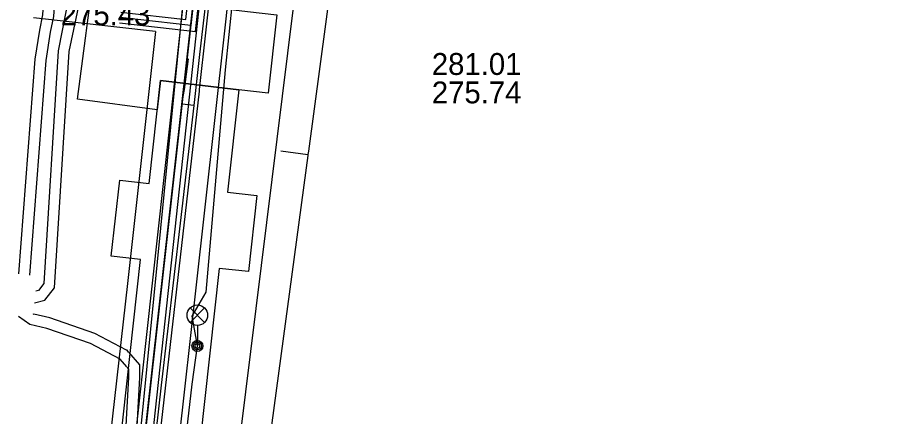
# Model space of a CAD drawing. Extents: x -595540 to -593988, y -1160850 to -1159202.
# Drawn here: x -594124.92 to -594093.22, y -1160478.95 to -1160464.35 of the extents above; entities that cross this region are included whole.
import ezdxf

# ---------------------------------------------------------------- set-up
doc = ezdxf.new("R2010")
doc.units = 0
for name, color, linetype in [('BVK-DESTOVA_popisy', 7, 'Continuous'), ('BVK-DESTOVA_trasa sítě', 7, 'Continuous'), ('BVK-SPLASKOVA_popisy', 7, 'Continuous'), ('BVK-SPLASKOVA_trasa sítě', 7, 'Continuous'), ('BVK-VODOVOD_trasa sítě', 7, 'Continuous'), ('BVK-VODOVOD_trasa zrušené sítě', 7, 'Continuous'), ('CETIN_kabel podzemní', 7, 'Continuous'), ('DESTOVA_trasa neprovozované sítě', 7, 'Continuous'), ('DSP-NN-TEPLARNY_kabel', 7, 'Continuous'), ('EON-NN_kabel', 7, 'Continuous'), ('EON-VN_kabel', 7, 'Continuous'), ('TEPLARNY-ELEKTRO_kabel', 7, 'Continuous'), ('TEPLARNY-HORKOVODY_trasa sítě', 7, 'Continuous'), ('TEPLARNY-HORKOVODY_trasa sítě obvodem', 7, 'Continuous'), ('TEPLARNY-TEPLOVODY_trasa sítě', 7, 'Continuous'), ('TSB_kabel VO', 7, 'Continuous'), ('TSB_kolektor', 7, 'Continuous'), ('TSB_lampy VO', 7, 'Continuous')]:
    doc.layers.add(name, color=color, linetype=linetype)

msp = doc.modelspace()

# ---------------------------------------------------------------- linework, layer by layer
at = {"layer": 'BVK-DESTOVA_trasa sítě'}
msp.add_lwpolyline([(-594112.859, -1160458.585), (-594114.291, -1160469.249), (-594114.307, -1160469.368), (-594114.311, -1160469.398), (-594115.794, -1160480.439), (-594115.833, -1160480.726), (-594115.841, -1160480.786), (-594118, -1160496.861), (-594118.004, -1160496.891), (-594118.009, -1160496.929)], dxfattribs=at)
at = {"layer": 'BVK-SPLASKOVA_popisy'}
msp.add_line((-594109.785, -1160465.658), (-594109.785, -1160465.658), dxfattribs=at)
at = {"layer": 'BVK-SPLASKOVA_trasa sítě'}
msp.add_lwpolyline([(-594114.091, -1160457.889), (-594116.975, -1160481.191), (-594117.014, -1160481.507), (-594118.999, -1160497.545)], dxfattribs=at)
at = {"layer": 'BVK-VODOVOD_trasa sítě'}
for points in [[(-594115.89, -1160444.6), (-594115.94, -1160445.07), (-594116.25, -1160447.88), (-594116.294, -1160448.264), (-594116.92, -1160453.82), (-594117.58, -1160459.76), (-594118.27, -1160465.71), (-594118.48, -1160467.58), (-594118.97, -1160471.88), (-594119.67, -1160477.8), (-594120.34, -1160483.75), (-594121.02, -1160489.68), (-594121.71, -1160495.66), (-594122.21, -1160500.14), (-594122.27, -1160500.66), (-594122.43, -1160502.17)], [(-594118.48, -1160467.58), (-594118.897, -1160467.533), (-594118.86, -1160467.25), (-594118.819, -1160466.987), (-594118.67, -1160465.87)]]:
    msp.add_lwpolyline(points, dxfattribs=at)
at = {"layer": 'BVK-VODOVOD_trasa zrušené sítě'}
msp.add_lwpolyline([(-594122.303, -1160501.51), (-594122.23, -1160501.03), (-594121.73, -1160497.28), (-594118.27, -1160467.05), (-594118.263, -1160466.995), (-594115.72, -1160444.2)], dxfattribs=at)
at = {"layer": 'CETIN_kabel podzemní'}
msp.add_lwpolyline([(-594120.66, -1160482.03), (-594118.21, -1160457.16)], dxfattribs=at)
at = {"layer": 'DESTOVA_trasa neprovozované sítě'}
msp.add_line((-594115.298, -1160469.235), (-594114.307, -1160469.368), dxfattribs=at)
at = {"layer": 'DSP-NN-TEPLARNY_kabel'}
for points in [[(-594121.143, -1160464.161), (-594118.761, -1160464.427), (-594112.865, -1160411.563), (-594119.56, -1160410.802), (-594119.143, -1160407.127), (-594112.454, -1160407.887), (-594102.843, -1160322.736), (-594109.531, -1160321.976), (-594109.114, -1160318.301), (-594102.425, -1160319.061), (-594092.133, -1160228.53), (-594097.433, -1160227.929), (-594097.016, -1160224.253), (-594091.712, -1160224.855), (-594085.261, -1160166.749), (-594090.048, -1160166.163), (-594089.626, -1160162.68), (-594084.872, -1160163.243), (-594081.459, -1160132.499), (-594087.185, -1160131.862)], [(-594121.187, -1160464.559), (-594118.408, -1160464.869), (-594112.423, -1160411.211), (-594119.118, -1160410.45), (-594118.791, -1160407.569), (-594112.102, -1160408.329), (-594102.401, -1160322.384), (-594109.089, -1160321.624), (-594108.762, -1160318.743), (-594102.073, -1160319.503), (-594091.691, -1160228.178)], [(-594091.912, -1160228.354), (-594102.249, -1160319.282), (-594108.938, -1160318.522), (-594109.31, -1160321.8), (-594102.622, -1160322.56), (-594112.278, -1160408.108), (-594118.967, -1160407.348), (-594119.339, -1160410.626), (-594112.644, -1160411.387), (-594118.584, -1160464.648), (-594121.165, -1160464.36)]]:
    msp.add_lwpolyline(points, dxfattribs=at)
at = {"layer": 'EON-NN_kabel'}
for points in [[(-594122.556, -1160445.471), (-594122.597, -1160445.497), (-594122.635, -1160445.889), (-594122.725, -1160446.581), (-594122.486, -1160449.163), (-594122.819, -1160455.327), (-594122.9, -1160461.145), (-594123.016, -1160463.453), (-594123.423, -1160465.583), (-594123.955, -1160474.087), (-594124.149, -1160474.335), (-594124.24, -1160474.359)], [(-594124.294, -1160474.785), (-594123.916, -1160474.688), (-594123.563, -1160474.235), (-594123.023, -1160465.599), (-594122.6, -1160463.579), (-594122.459, -1160460.04), (-594122.421, -1160455.361), (-594122.086, -1160449.177), (-594122.302, -1160446.415), (-594122.222, -1160445.838), (-594122.208, -1160445.663)], [(-594128.953, -1160460.346), (-594128.245, -1160459.666), (-594123.859, -1160460.158), (-594123.491, -1160460.525), (-594123.391, -1160461.016), (-594123.597, -1160464.318), (-594123.719, -1160464.893), (-594123.881, -1160465.933), (-594124.479, -1160473.774)], [(-594128.446, -1160460.412), (-594128.103, -1160460.084), (-594124.043, -1160460.54), (-594123.859, -1160460.723), (-594123.794, -1160461.05), (-594123.994, -1160464.264), (-594124.113, -1160464.821), (-594124.279, -1160465.887), (-594124.876, -1160473.724)], [(-594120.918, -1160477.133), (-594121.168, -1160476.842), (-594122.25, -1160476.275), (-594123.841, -1160475.726), (-594124.463, -1160475.579), (-594124.879, -1160475.286)], [(-594120.858, -1160476.589), (-594120.914, -1160476.524), (-594120.93, -1160476.515), (-594122.091, -1160475.907), (-594123.73, -1160475.341), (-594124.316, -1160475.203), (-594124.347, -1160475.211)], [(-594120.86, -1160476.587), (-594120.454, -1160477.06), (-594120.454, -1160477.521), (-594120.631, -1160480.626), (-594120.758, -1160482.853), (-594120.909, -1160484.458), (-594121.245, -1160487.388), (-594121.808, -1160492.605), (-594122.21, -1160496.156), (-594122.252, -1160498.234), (-594122.328, -1160499.594), (-594122.85, -1160502.414), (-594122.986, -1160503.122)], [(-594120.916, -1160477.135), (-594120.854, -1160477.208), (-594120.854, -1160477.509), (-594121.031, -1160480.604), (-594121.156, -1160482.823), (-594121.307, -1160484.416), (-594121.643, -1160487.344), (-594122.206, -1160492.561), (-594122.61, -1160496.13), (-594122.652, -1160498.218), (-594122.726, -1160499.546), (-594123.244, -1160502.34), (-594123.385, -1160503.08)]]:
    msp.add_lwpolyline(points, dxfattribs=at)
at = {"layer": 'EON-VN_kabel'}
for points in [[(-594095.349, -1160247.589), (-594106.321, -1160343.506), (-594106.366, -1160343.901), (-594106.457, -1160344.697), (-594105.747, -1160344.778), (-594123.196, -1160503.1)], [(-594122.533, -1160503.17), (-594105.303, -1160344.425), (-594106.002, -1160344.346), (-594105.957, -1160343.948), (-594105.911, -1160343.552), (-594094.954, -1160247.658)]]:
    msp.add_lwpolyline(points, dxfattribs=at)
at = {"layer": 'TEPLARNY-ELEKTRO_kabel'}
for points in [[(-594121.143, -1160464.161), (-594118.761, -1160464.427), (-594112.865, -1160411.563), (-594119.56, -1160410.802), (-594119.143, -1160407.127), (-594112.454, -1160407.887), (-594102.843, -1160322.736), (-594109.531, -1160321.976), (-594109.114, -1160318.301), (-594102.425, -1160319.061), (-594092.133, -1160228.53), (-594097.433, -1160227.929), (-594097.016, -1160224.253), (-594091.712, -1160224.855), (-594085.261, -1160166.749), (-594090.048, -1160166.163), (-594089.626, -1160162.68), (-594084.872, -1160163.243), (-594081.459, -1160132.499), (-594087.185, -1160131.862)], [(-594121.187, -1160464.559), (-594118.408, -1160464.869), (-594112.423, -1160411.211), (-594119.118, -1160410.45), (-594118.791, -1160407.569), (-594112.102, -1160408.329), (-594102.401, -1160322.384), (-594109.089, -1160321.624), (-594108.762, -1160318.743), (-594102.073, -1160319.503), (-594091.691, -1160228.178)], [(-594091.912, -1160228.354), (-594102.249, -1160319.282), (-594108.938, -1160318.522), (-594109.31, -1160321.8), (-594102.622, -1160322.56), (-594112.278, -1160408.108), (-594118.967, -1160407.348), (-594119.339, -1160410.626), (-594112.644, -1160411.387), (-594118.584, -1160464.648), (-594121.165, -1160464.36)]]:
    msp.add_lwpolyline(points, dxfattribs=at)
at = {"layer": 'TEPLARNY-HORKOVODY_trasa sítě'}
for p, q in [((-594118.492, -1160463.766), (-594119.659, -1160474.215)), ((-594119.659, -1160474.215), (-594122.628, -1160500.798))]:
    msp.add_line(p, q, dxfattribs=at)
at = {"layer": 'TEPLARNY-HORKOVODY_trasa sítě obvodem'}
for p, q in [((-594114.916, -1160442.994), (-594117.369, -1160464.959)), ((-594119.874, -1160464.868), (-594124.325, -1160464.368)), ((-594119.874, -1160464.868), (-594120.902, -1160474.076)), ((-594117.369, -1160464.959), (-594118.418, -1160474.354)), ((-594120.902, -1160474.076), (-594123.939, -1160501.282)), ((-594118.418, -1160474.354), (-594121.317, -1160500.314))]:
    msp.add_line(p, q, dxfattribs=at)
at = {"layer": 'TEPLARNY-TEPLOVODY_trasa sítě'}
msp.add_lwpolyline([(-594118.533, -1160464.056), (-594120.423, -1160480.943), (-594122.643, -1160500.777), (-594146.3, -1160497.939)], dxfattribs=at)
at = {"layer": 'TSB_kabel VO'}
msp.add_lwpolyline([(-594119.13, -1160482.95), (-594118.54, -1160477.76), (-594118.345, -1160476.366), (-594118.53, -1160475.28), (-594118.03, -1160474.4), (-594117.32, -1160466.27), (-594117.05, -1160463.68), (-594116.52, -1160460.6), (-594116.559, -1160459.42), (-594118.018, -1160458.247), (-594123.237, -1160458.036), (-594123.181, -1160457.489), (-594122.139, -1160448.947), (-594121.383, -1160445.991), (-594120.533, -1160445.877), (-594120.523, -1160444.982), (-594120.12, -1160445.03), (-594117.23, -1160445.35), (-594116.44, -1160439.53), (-594115.77, -1160439.63)], dxfattribs=at)
at = {"layer": 'TSB_kolektor'}
msp.add_lwpolyline([(-594115.445, -1160464.264), (-594115.766, -1160467.127), (-594116.836, -1160467.007), (-594119.696, -1160466.66), (-594119.814, -1160467.737), (-594122.722, -1160467.348), (-594122.072, -1160462.412), (-594119.261, -1160462.726), (-594119.381, -1160463.797), (-594116.521, -1160464.145)], close=True, dxfattribs=at)
msp.add_lwpolyline([(-594123.088, -1160497.479), (-594120.416, -1160473.209), (-594121.492, -1160473.088), (-594121.181, -1160470.305), (-594120.11, -1160470.425), (-594119.696, -1160466.66), (-594116.836, -1160467.007), (-594117.248, -1160470.746), (-594116.172, -1160470.866), (-594116.484, -1160473.649), (-594117.554, -1160473.529), (-594120.511, -1160500.391)], dxfattribs=at)
at = {"layer": 'TSB_lampy VO'}
for p, q in [((-594118.61, -1160475.506), (-594118.08, -1160474.976)), ((-594118.61, -1160474.976), (-594118.08, -1160475.506)), ((-594118.61, -1160475.506), (-594118.08, -1160474.976)), ((-594118.61, -1160474.976), (-594118.08, -1160475.506)), ((-594118.345, -1160475.616), (-594118.345, -1160476.366)), ((-594118.345, -1160475.616), (-594118.345, -1160476.366))]:
    msp.add_line(p, q, dxfattribs=at)
for centre, radius in [((-594118.345, -1160475.241), 0.375), ((-594118.345, -1160475.241), 0.375), ((-594118.345, -1160476.366), 0.2), ((-594118.345, -1160476.366), 0.2), ((-594118.345, -1160476.366), 0.145), ((-594118.345, -1160476.366), 0.145), ((-594118.345, -1160476.366), 0.0876), ((-594118.345, -1160476.366), 0.0876)]:
    msp.add_circle(centre, radius, dxfattribs=at)

# ---------------------------------------------------------------- texts
at = {"layer": 'BVK-DESTOVA_popisy'}
msp.add_text('275.43', height=0.8, dxfattribs=at).set_placement((-594123.333, -1160464.644))
at = {"layer": 'BVK-SPLASKOVA_popisy'}
for s, p in [('281.01', (-594109.785, -1160466.458)), ('275.74', (-594109.785, -1160467.498))]:
    msp.add_text(s, height=0.8, dxfattribs=at).set_placement(p)

doc.saveas('drawing.dxf')
